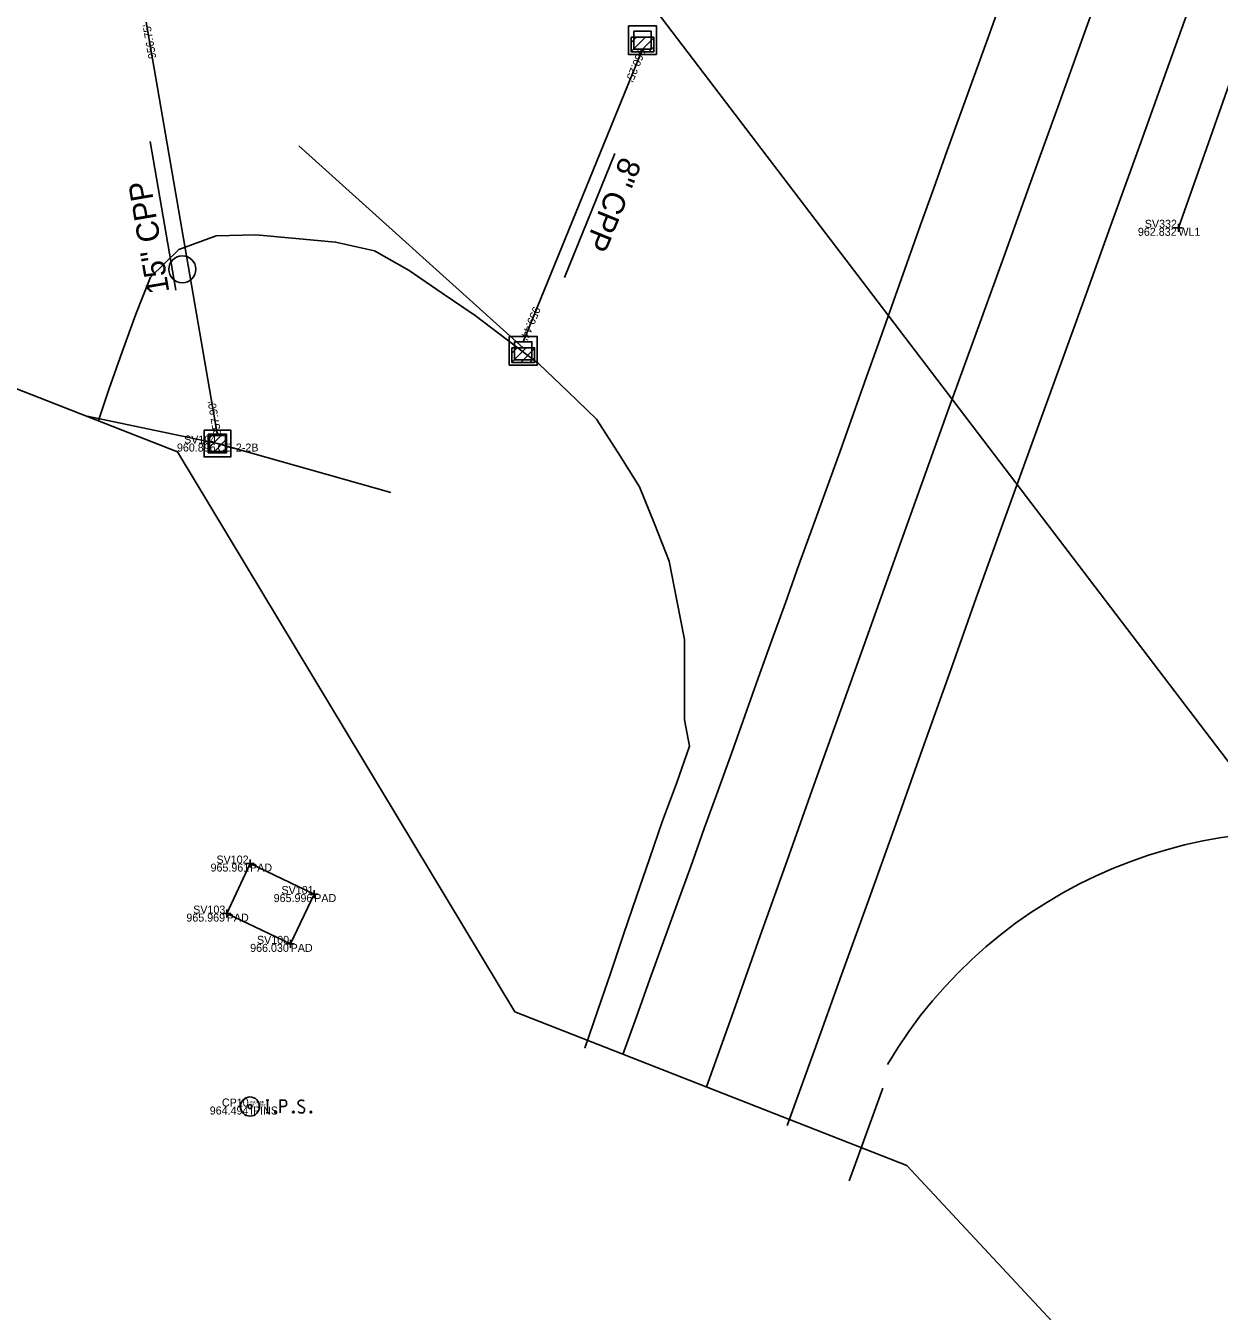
# Model space of a CAD drawing. Extents: x 2262025 to 2264532, y 740981 to 742724.
# Drawn here: x 2262914.1 to 2263063.3, y 741437.6 to 741598.2 of the extents above; entities that cross this region are included whole.
import ezdxf

# ---------------------------------------------------------------- set-up
doc = ezdxf.new("R2010")
doc.units = 0
for name, color, linetype in [('DR_X_Storm_Sewer', 7, 'Continuous'), ('DR_X_Text', 7, 'Continuous'), ('GE_X_Alignment_100_Cardinal_Points', 7, 'Continuous'), ('GE_X_Alignment_100_Curve_Data', 7, 'Continuous'), ('GE_X_Alignment_100_Stations', 7, 'Continuous'), ('GE_X_Alignment_500_Bearings', 7, 'Continuous'), ('HY_X_Spring_Cells', 7, 'Continuous'), ('RS_Raster1', 7, 'Continuous'), ('RW_X_CL', 7, 'Continuous'), ('RW_X_CL_1000_Bearings', 7, 'Continuous'), ('RW_X_CL_1000_Distances', 7, 'Continuous'), ('RW_X_CL_1000_Stations', 7, 'Continuous'), ('RW_X_CL_100_Bearings', 7, 'Continuous'), ('RW_X_CL_100_Cardinal_Points', 7, 'Continuous'), ('RW_X_CL_100_Curve_Data', 7, 'Continuous'), ('RW_X_CL_100_Stations', 7, 'Continuous'), ('RW_X_CL_500_Curve_Data', 7, 'Continuous'), ('RW_X_CL_500_Stations', 7, 'Continuous'), ('SC_Scratch4', 7, 'Continuous'), ('SV_X_Text_Comment', 7, 'Continuous'), ('UT_X_Water', 7, 'Continuous')]:
    doc.layers.add(name, color=color, linetype=linetype)

msp = doc.modelspace()

# ---------------------------------------------------------------- linework, layer by layer
at = {"layer": 'DR_X_Storm_Sewer'}
for p, q in [((2262952, 741653.76), (2263353.07, 741127.49)), ((2262938.08, 741547.02), (2262929.17, 741598.66)), ((2262991.19, 741595.29), (2262976.3, 741558.74))]:
    msp.add_line(p, q, dxfattribs=at)
at = {"layer": 'DR_X_Text'}
for p, q in [((2262929.68, 741583.77), (2262932.89, 741565.17)), ((2262981.45, 741566.78), (2262987.75, 741582.24))]:
    msp.add_line(p, q, dxfattribs=at)
at = {"layer": 'GE_X_Alignment_100_Cardinal_Points'}
msp.add_lwpolyline([(2263021.26, 741465.48), (2263017.84, 741456.08), (2263017.05, 741453.9)], dxfattribs=at)
at = {"layer": 'GE_X_Alignment_100_Curve_Data'}
msp.add_lwpolyline([(2262983.99, 741470.5), (2262985.61, 741475.23), (2262987.23, 741479.96), (2262988.85, 741484.69), (2262990.47, 741489.43), (2262992.09, 741494.16), (2262993.71, 741498.89), (2262995.46, 741503.56), (2262997.08, 741508.22), (2262996.45, 741511.52)], dxfattribs=at)
at = {"layer": 'GE_X_Alignment_100_Stations'}
msp.add_circle((2262933.7, 741567.79), 1.69, dxfattribs=at)
at = {"layer": 'GE_X_Alignment_500_Bearings'}
msp.add_lwpolyline([(2262996.45, 741511.52), (2262996.45, 741516.52), (2262996.45, 741521.52), (2262995.51, 741526.42), (2262994.52, 741531.32), (2262992.69, 741535.97), (2262990.81, 741540.61), (2262988.16, 741544.84), (2262985.47, 741549.06), (2262981.88, 741552.53), (2262978.26, 741555.97), (2262974.28, 741558.99), (2262970.29, 741562), (2262966.17, 741564.82), (2262962.05, 741567.64), (2262957.7, 741570.1), (2262952.84, 741571.19), (2262947.87, 741571.65), (2262942.89, 741572.1), (2262937.91, 741571.95), (2262933.26, 741570.26), (2262929.71, 741566.79), (2262927.88, 741562.17), (2262926.18, 741557.47), (2262924.52, 741552.76), (2262923.16, 741548.78)], dxfattribs=at)
msp.add_arc((2263072.86, 741438.14), 59.38, 2.4818, 149.2858, dxfattribs=at)
at = {"layer": 'RS_Raster1'}
msp.add_lwpolyline([(2262680.86, 741714.81), (2262661.07, 741645.79), (2262765.42, 741624.79), (2262779.22, 741624.19), (2262826.51, 741606.02), (2262832.34, 741584.41), (2262933.09, 741544.98), (2262975.25, 741475.03), (2263024.25, 741455.82), (2263090.74, 741384.5), (2263137.01, 741437.31), (2263272.72, 741623.51), (2263304.66, 741651.89), (2263427.06, 741723.41), (2263444.69, 741740.07), (2263470.34, 741746.73), (2263467.01, 741806.69), (2263433.84, 741893.93), (2263732.51, 742061.95)], dxfattribs=at)
at = {"layer": 'RW_X_CL_1000_Bearings'}
msp.add_line((2262942.15, 741463.2), (2262942.15, 741463.2), dxfattribs=at)
msp.add_line((2262942.15, 741463.2), (2262942.15, 741463.2), dxfattribs=at)
msp.add_line((2262942.15, 741463.2), (2262942.15, 741463.2), dxfattribs=at)
at = {"layer": 'RW_X_CL_1000_Distances'}
for points in [[(2262988.74, 741469.69), (2262990.44, 741474.39), (2262992.14, 741479.09), (2262993.83, 741483.8), (2262995.53, 741488.5), (2262997.23, 741493.2), (2262998.93, 741497.91), (2263000.62, 741502.61), (2263002.31, 741507.32), (2263004, 741512.02), (2263005.68, 741516.73), (2263007.37, 741521.44), (2263009.06, 741526.14), (2263010.75, 741530.85), (2263012.46, 741535.55), (2263014.17, 741540.25), (2263015.86, 741544.95), (2263017.55, 741549.65), (2263019.22, 741554.37), (2263020.89, 741559.08), (2263022.56, 741563.79), (2263024.23, 741568.5), (2263025.91, 741573.21), (2263027.6, 741577.92), (2263029.3, 741582.62), (2263031, 741587.32), (2263032.7, 741592.03), (2263034.39, 741596.73), (2263036.07, 741601.44)], [(2263009.29, 741460.83), (2263012.69, 741470.24), (2263016.09, 741479.64), (2263019.49, 741489.05), (2263022.85, 741498.46), (2263026.21, 741507.88), (2263029.56, 741517.3), (2263032.9, 741526.73), (2263036.3, 741536.13), (2263039.71, 741545.53), (2263043.13, 741554.93), (2263046.53, 741564.34), (2263049.92, 741573.74), (2263053.31, 741583.15), (2263056.68, 741592.57), (2263060.06, 741601.98)]]:
    msp.add_lwpolyline(points, dxfattribs=at)
at = {"layer": 'RW_X_CL_1000_Stations'}
msp.add_line((2262942.15, 741463.2), (2262942.15, 741463.2), dxfattribs=at)
msp.add_line((2262942.15, 741463.2), (2262942.15, 741463.2), dxfattribs=at)
msp.add_line((2262942.15, 741463.2), (2262942.15, 741463.2), dxfattribs=at)
msp.add_circle((2262942.15, 741463.2), 0.25, dxfattribs=at)
msp.add_circle((2262942.15, 741463.2), 0.25, dxfattribs=at)
msp.add_circle((2262942.15, 741463.2), 0.25, dxfattribs=at)
at = {"layer": 'RW_X_CL_100_Bearings'}
for points in [[(2262944.17, 741464), (2262944.52, 741464)], [(2262944.34, 741462.4), (2262944.34, 741464)], [(2262945.3, 741462.61), (2262945.36, 741462.61), (2262945.39, 741462.59), (2262945.42, 741462.54), (2262945.42, 741462.47), (2262945.39, 741462.42), (2262945.36, 741462.4), (2262945.3, 741462.4), (2262945.27, 741462.42), (2262945.24, 741462.47), (2262945.24, 741462.54), (2262945.27, 741462.59), (2262945.3, 741462.61)], [(2262945.91, 741462.4), (2262945.91, 741464), (2262946.44, 741464), (2262946.49, 741463.99), (2262946.57, 741463.96), (2262946.6, 741463.94), (2262946.64, 741463.91), (2262946.68, 741463.85), (2262946.71, 741463.78), (2262946.73, 741463.68), (2262946.73, 741463.53), (2262946.72, 741463.48), (2262946.7, 741463.41), (2262946.66, 741463.32), (2262946.61, 741463.28), (2262946.58, 741463.25), (2262946.52, 741463.23), (2262946.44, 741463.22), (2262945.91, 741463.22)], [(2262947.55, 741462.61), (2262947.61, 741462.61), (2262947.64, 741462.59), (2262947.67, 741462.54), (2262947.67, 741462.47), (2262947.64, 741462.42), (2262947.61, 741462.4), (2262947.55, 741462.4), (2262947.52, 741462.42), (2262947.48, 741462.47), (2262947.48, 741462.54), (2262947.52, 741462.59), (2262947.55, 741462.61)], [(2262948.92, 741463.88), (2262948.89, 741463.91), (2262948.86, 741463.94), (2262948.76, 741463.97), (2262948.64, 741464), (2262948.55, 741464), (2262948.52, 741464), (2262948.38, 741463.96), (2262948.26, 741463.88), (2262948.18, 741463.78), (2262948.16, 741463.68), (2262948.16, 741463.61), (2262948.18, 741463.51), (2262948.27, 741463.42), (2262948.87, 741463.04), (2262948.93, 741462.99), (2262948.95, 741462.94), (2262948.97, 741462.86), (2262948.97, 741462.79), (2262948.96, 741462.71), (2262948.95, 741462.66), (2262948.93, 741462.6), (2262948.91, 741462.55), (2262948.88, 741462.51), (2262948.85, 741462.47), (2262948.82, 741462.45), (2262948.77, 741462.42), (2262948.74, 741462.41), (2262948.64, 741462.4), (2262948.49, 741462.4), (2262948.39, 741462.42), (2262948.24, 741462.51), (2262948.16, 741462.59)], [(2262949.73, 741462.61), (2262949.79, 741462.61), (2262949.82, 741462.59), (2262949.85, 741462.54), (2262949.85, 741462.47), (2262949.82, 741462.42), (2262949.79, 741462.4), (2262949.73, 741462.4), (2262949.7, 741462.42), (2262949.67, 741462.47), (2262949.67, 741462.54), (2262949.7, 741462.59), (2262949.73, 741462.61)], [(2262944.17, 741462.4), (2262944.52, 741462.4)]]:
    msp.add_lwpolyline(points, dxfattribs=at)
msp.add_circle((2262942.15, 741463.2), 1.2, dxfattribs=at)
at = {"layer": 'RW_X_CL_100_Cardinal_Points'}
for p, q in [((2263058.18, 741573.47), (2263058.18, 741572.47)), ((2263057.68, 741572.97), (2263058.68, 741572.97)), ((2263058.18, 741572.97), (2263058.18, 741572.97)), ((2262941.66, 741493.55), (2262942.66, 741493.55)), ((2262942.16, 741494.05), (2262942.16, 741493.05)), ((2262942.16, 741493.55), (2262942.16, 741493.55)), ((2262950.18, 741490.24), (2262950.18, 741489.24)), ((2262949.68, 741489.74), (2262950.68, 741489.74)), ((2262950.18, 741489.74), (2262950.18, 741489.74)), ((2262938.74, 741487.3), (2262939.74, 741487.3)), ((2262939.24, 741487.8), (2262939.24, 741486.8)), ((2262939.24, 741487.3), (2262939.24, 741487.3)), ((2262946.73, 741483.52), (2262947.73, 741483.52)), ((2262947.23, 741484.02), (2262947.23, 741483.02)), ((2262947.23, 741483.52), (2262947.23, 741483.52))]:
    msp.add_line(p, q, dxfattribs=at)
at = {"layer": 'RW_X_CL_100_Curve_Data'}
for p, q in [((2262989.77, 741594.99), (2262991.57, 741596.79)), ((2262989.77, 741596.12), (2262990.44, 741596.79)), ((2262989.77, 741594.99), (2262991.57, 741596.79)), ((2262989.77, 741596.12), (2262990.44, 741596.79)), ((2262990.87, 741594.96), (2262992.61, 741596.7)), ((2262990.87, 741594.96), (2262992.61, 741596.7)), ((2262992, 741594.96), (2262992.61, 741595.56)), ((2262992, 741594.96), (2262992.61, 741595.56)), ((2262974.88, 741556.19), (2262976.68, 741557.99)), ((2262974.88, 741557.32), (2262975.55, 741557.99)), ((2262974.88, 741556.19), (2262976.68, 741557.99)), ((2262974.88, 741557.32), (2262975.55, 741557.99)), ((2262975.98, 741556.15), (2262977.72, 741557.89)), ((2262975.98, 741556.15), (2262977.72, 741557.89)), ((2262977.11, 741556.15), (2262977.72, 741556.76)), ((2262977.11, 741556.15), (2262977.72, 741556.76)), ((2262936.94, 741545.41), (2262938.7, 741547.17)), ((2262936.94, 741546.54), (2262937.56, 741547.17)), ((2262936.94, 741545.41), (2262938.7, 741547.17)), ((2262936.94, 741546.54), (2262937.56, 741547.17)), ((2262937.54, 741544.87), (2262939.23, 741546.57)), ((2262937.54, 741544.87), (2262939.23, 741546.57)), ((2262938.67, 741544.87), (2262939.23, 741545.44)), ((2262938.67, 741544.87), (2262939.23, 741545.44))]:
    msp.add_line(p, q, dxfattribs=at)
for points in [[(2262989.44, 741598.21), (2262992.94, 741598.21), (2262992.94, 741594.63), (2262989.44, 741594.63)], [(2262989.44, 741598.21), (2262992.94, 741598.21), (2262992.94, 741594.63), (2262989.44, 741594.63)], [(2262990.11, 741597.54), (2262992.27, 741597.54), (2262992.27, 741595.29), (2262990.11, 741595.29)], [(2262990.11, 741597.54), (2262992.27, 741597.54), (2262992.27, 741595.29), (2262990.11, 741595.29)], [(2262989.77, 741596.79), (2262992.61, 741596.79), (2262992.61, 741594.96), (2262989.77, 741594.96)], [(2262989.77, 741596.79), (2262992.61, 741596.79), (2262992.61, 741594.96), (2262989.77, 741594.96)], [(2262974.55, 741559.4), (2262978.05, 741559.4), (2262978.05, 741555.82), (2262974.55, 741555.82)], [(2262974.55, 741559.4), (2262978.05, 741559.4), (2262978.05, 741555.82), (2262974.55, 741555.82)], [(2262974.88, 741557.99), (2262977.72, 741557.99), (2262977.72, 741556.15), (2262974.88, 741556.15)], [(2262974.88, 741557.99), (2262977.72, 741557.99), (2262977.72, 741556.15), (2262974.88, 741556.15)], [(2262975.22, 741558.74), (2262977.38, 741558.74), (2262977.38, 741556.49), (2262975.22, 741556.49)], [(2262975.22, 741558.74), (2262977.38, 741558.74), (2262977.38, 741556.49), (2262975.22, 741556.49)], [(2262936.42, 741547.69), (2262939.75, 741547.69), (2262939.75, 741544.35), (2262936.42, 741544.35)], [(2262936.42, 741547.69), (2262939.75, 741547.69), (2262939.75, 741544.35), (2262936.42, 741544.35)], [(2262936.94, 741547.17), (2262939.23, 741547.17), (2262939.23, 741544.87), (2262936.94, 741544.87)], [(2262936.94, 741547.17), (2262939.23, 741547.17), (2262939.23, 741544.87), (2262936.94, 741544.87)], [(2262937.08, 741547.02), (2262939.08, 741547.02), (2262939.08, 741545.02), (2262937.08, 741545.02)], [(2262937.08, 741547.02), (2262939.08, 741547.02), (2262939.08, 741545.02), (2262937.08, 741545.02)]]:
    msp.add_lwpolyline(points, close=True, dxfattribs=at)
at = {"layer": 'RW_X_CL_100_Stations'}
for p, q in [((2262991.19, 741598.21), (2262991.19, 741598.21)), ((2262991.19, 741598.21), (2262991.19, 741598.21)), ((2262991.19, 741597.54), (2262991.19, 741597.54)), ((2262991.19, 741597.54), (2262991.19, 741597.54)), ((2262990.11, 741596.42), (2262990.11, 741596.42)), ((2262990.11, 741596.42), (2262990.11, 741596.42)), ((2262991.19, 741596.79), (2262991.19, 741596.79)), ((2262991.19, 741596.79), (2262991.19, 741596.79)), ((2262991.19, 741596.79), (2262991.19, 741596.79)), ((2262991.19, 741596.79), (2262991.19, 741596.79)), ((2262991.19, 741596.42), (2262991.19, 741596.42)), ((2262991.19, 741596.42), (2262991.19, 741596.42)), ((2262991.19, 741596.42), (2262991.19, 741596.42)), ((2262991.19, 741596.42), (2262991.19, 741596.42)), ((2262992.27, 741596.42), (2262992.27, 741596.42)), ((2262992.27, 741596.42), (2262992.27, 741596.42)), ((2262991.19, 741595.29), (2262991.19, 741595.29)), ((2262991.19, 741595.29), (2262991.19, 741595.29)), ((2262991.19, 741594.63), (2262991.19, 741594.63)), ((2262991.19, 741594.63), (2262991.19, 741594.63)), ((2262976.3, 741559.4), (2262976.3, 741559.4)), ((2262976.3, 741559.4), (2262976.3, 741559.4)), ((2262975.22, 741557.61), (2262975.22, 741557.61)), ((2262975.22, 741557.61), (2262975.22, 741557.61)), ((2262976.3, 741558.74), (2262976.3, 741558.74)), ((2262976.3, 741558.74), (2262976.3, 741558.74)), ((2262976.3, 741557.99), (2262976.3, 741557.99)), ((2262976.3, 741557.99), (2262976.3, 741557.99)), ((2262976.3, 741557.99), (2262976.3, 741557.99)), ((2262976.3, 741557.99), (2262976.3, 741557.99)), ((2262976.3, 741557.61), (2262976.3, 741557.61)), ((2262976.3, 741557.61), (2262976.3, 741557.61)), ((2262976.3, 741557.61), (2262976.3, 741557.61)), ((2262976.3, 741557.61), (2262976.3, 741557.61)), ((2262977.38, 741557.61), (2262977.38, 741557.61)), ((2262977.38, 741557.61), (2262977.38, 741557.61)), ((2262976.3, 741556.49), (2262976.3, 741556.49)), ((2262976.3, 741556.49), (2262976.3, 741556.49)), ((2262976.3, 741555.82), (2262976.3, 741555.82)), ((2262976.3, 741555.82), (2262976.3, 741555.82)), ((2262938.08, 741547.69), (2262938.08, 741547.69)), ((2262938.08, 741547.69), (2262938.08, 741547.69)), ((2262937.08, 741546.02), (2262937.08, 741546.02)), ((2262937.08, 741546.02), (2262937.08, 741546.02)), ((2262938.08, 741547.02), (2262938.08, 741547.02)), ((2262938.08, 741547.02), (2262938.08, 741547.02)), ((2262938.08, 741546.02), (2262938.08, 741546.02)), ((2262938.08, 741546.02), (2262938.08, 741546.02)), ((2262938.08, 741546.02), (2262938.08, 741546.02)), ((2262938.08, 741546.02), (2262938.08, 741546.02)), ((2262938.08, 741546.02), (2262938.08, 741546.02)), ((2262938.08, 741546.02), (2262938.08, 741546.02)), ((2262939.08, 741546.02), (2262939.08, 741546.02)), ((2262939.08, 741546.02), (2262939.08, 741546.02)), ((2262938.08, 741545.02), (2262938.08, 741545.02)), ((2262938.08, 741545.02), (2262938.08, 741545.02)), ((2262938.08, 741544.35), (2262938.08, 741544.35)), ((2262938.08, 741544.35), (2262938.08, 741544.35))]:
    msp.add_line(p, q, dxfattribs=at)
at = {"layer": 'RW_X_CL_500_Curve_Data'}
msp.add_lwpolyline([(2262947.23, 741483.52), (2262950.18, 741489.74), (2262942.16, 741493.55), (2262939.24, 741487.3)], close=True, dxfattribs=at)
at = {"layer": 'RW_X_CL_500_Stations'}
for p, q in [((2262976.3, 741557.99), (2262948.25, 741583.19)), ((2262921.58, 741549.5), (2262938.08, 741546.02)), ((2262959.77, 741539.89), (2262938.08, 741546.02))]:
    msp.add_line(p, q, dxfattribs=at)
at = {"layer": 'SC_Scratch4'}
msp.add_lwpolyline([(2262999.22, 741465.67), (2263002.58, 741475.09), (2263005.93, 741484.51), (2263009.28, 741493.93), (2263012.63, 741503.35), (2263015.99, 741512.77), (2263019.37, 741522.18), (2263022.75, 741531.6), (2263026.13, 741541.01), (2263029.51, 741550.42), (2263032.91, 741559.82), (2263036.31, 741569.23), (2263039.7, 741578.63), (2263043.1, 741588.04), (2263046.5, 741597.44), (2263049.91, 741606.85)], dxfattribs=at)
at = {"layer": 'UT_X_Water'}
msp.add_lwpolyline([(2263058.18, 741572.97), (2263085.82, 741651.25), (2263095.93, 741679.99), (2263097.95, 741685.82), (2263106.82, 741712.78), (2263147.36, 741828.66), (2263178.07, 741920.18), (2263217.98, 742032.49), (2263252.6, 742127.99), (2263295.63, 742247.6), (2263334.95, 742356.22), (2263370.78, 742449.55), (2263413.67, 742573.04), (2263421.38, 742593.43)], dxfattribs=at)

# ---------------------------------------------------------------- texts
at = {"layer": 'DR_X_Text'}
for s, rotation, p in [('8" CPP', 247.8358, (2262988.53, 741581.99)), ('15" CPP', 99.7972, (2262932.09, 741564.97))]:
    msp.add_text(s, height=2.8, rotation=rotation, dxfattribs=at).set_placement(p)
at = {"layer": 'HY_X_Spring_Cells'}
for s, p in [('962.832', (2263053.12, 741571.97)), ('960.896', (2262933.02, 741545.02)), ('960.896', (2262933.02, 741545.02)), ('965.961', (2262937.22, 741492.55)), ('965.996', (2262945.11, 741488.74)), ('965.969', (2262934.2, 741486.3)), ('966.030', (2262942.17, 741482.52)), ('964.494', (2262937.12, 741462.2))]:
    msp.add_text(s, height=1, dxfattribs=at).set_placement(p)
at = {"layer": 'RS_Raster1'}
for s, rotation, p in [("956.75'", 99.7972, (2262930.45, 741594.18)), ("960.25'", 247.8358, (2262990.73, 741595.48)), ("959.44'", 247.8358, (2262977.58, 741563.22)), ("957.90'", 99.7972, (2262938.58, 741547.11))]:
    msp.add_text(s, height=1, rotation=rotation, dxfattribs=at).set_placement(p)
at = {"layer": 'RW_X_CL'}
for s, p in [('WL1', (2263058.18, 741571.97)), ('CB-2-2B', (2262938.08, 741545.02)), ('CB-2-2B', (2262938.08, 741545.02)), ('PAD', (2262942.16, 741492.55)), ('PAD', (2262950.18, 741488.74)), ('PAD', (2262939.24, 741486.3)), ('PAD', (2262947.23, 741482.52)), ('IPINS', (2262942.15, 741462.2))]:
    msp.add_text(s, height=1, dxfattribs=at).set_placement(p)
at = {"layer": 'RW_X_CL_1000_Stations'}
for s, p in [('ΔZ: -1.057', (2262942.15, 741463.2)), ('ΔZ: -1.057', (2262942.15, 741463.2)), ('ΔZ: -1.057', (2262942.15, 741463.2)), ('Index: 51', (2262942.15, 741463.6)), ('Index: 60', (2262942.15, 741463.6)), ('Index: 69', (2262942.15, 741463.6))]:
    msp.add_text(s, height=0.3, dxfattribs=at).set_placement(p)
at = {"layer": 'SV_X_Text_Comment'}
for s, p in [('SV332', (2263053.98, 741572.97)), ('SV104', (2262933.91, 741546.02)), ('SV104', (2262933.91, 741546.02)), ('SV102', (2262937.96, 741493.55)), ('SV101', (2262946.09, 741489.74)), ('SV103', (2262935.05, 741487.3)), ('SV100', (2262943.02, 741483.52)), ('CP10', (2262938.64, 741463.2))]:
    msp.add_text(s, height=1, dxfattribs=at).set_placement(p)

doc.saveas('drawing.dxf')
